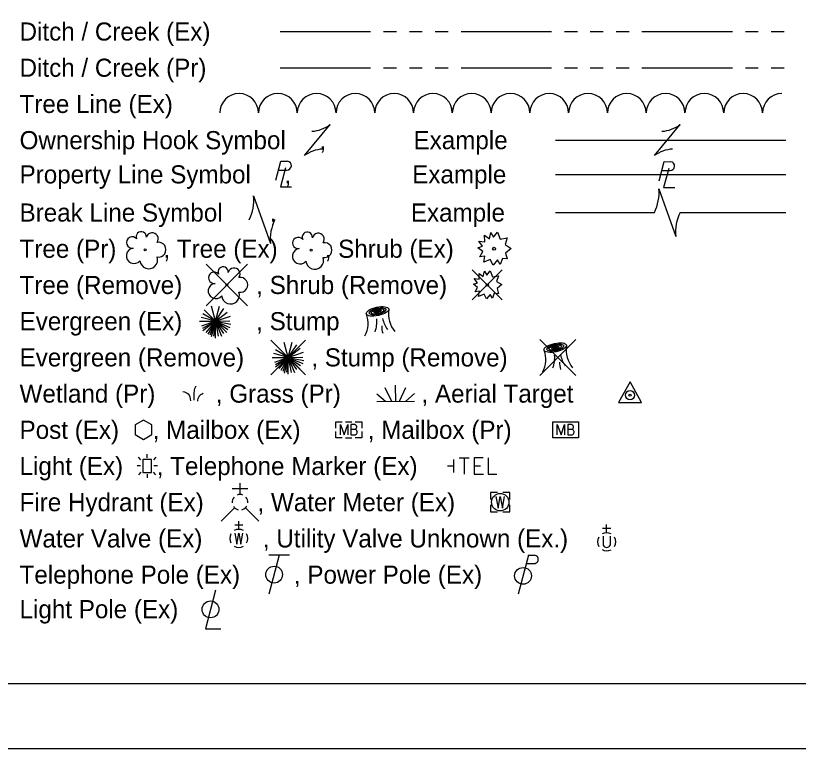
# Model space of a CAD drawing. Extents: x 0 to 34, y 0 to 22.
# Drawn here: x 8.23 to 14.29, y 0 to 5.67 of the extents above; entities that cross this region are included whole.
import ezdxf

# ---------------------------------------------------------------- set-up
doc = ezdxf.new("R2010")
doc.units = 0
for name, color, linetype in [('SH_Border', 7, 'Continuous'), ('SH_Cut_Line', 7, 'Continuous'), ('SH_Text', 7, 'Continuous')]:
    doc.layers.add(name, color=color, linetype=linetype)

msp = doc.modelspace()

# ---------------------------------------------------------------- linework, layer by layer
at = {"layer": 'SH_Border'}
msp.add_lwpolyline([(1.5, 21.5), (33.5, 21.5), (33.5, 0.5), (1.5, 0.5)], close=True, dxfattribs=at)
at = {"layer": 'SH_Cut_Line'}
msp.add_lwpolyline([(0, 0), (34, 0), (34, 22), (0, 22)], close=True, dxfattribs=at)
at = {"layer": 'SH_Text'}
for p, q in [((10.28, 5.5434), (10.98, 5.5434)), ((11.08, 5.5434), (11.18, 5.5434)), ((11.28, 5.5434), (11.38, 5.5434)), ((11.48, 5.5434), (11.58, 5.5434)), ((11.68, 5.5434), (12.38, 5.5434)), ((12.48, 5.5434), (12.58, 5.5434)), ((12.68, 5.5434), (12.78, 5.5434)), ((12.88, 5.5434), (12.98, 5.5434)), ((13.08, 5.5434), (13.78, 5.5434)), ((13.88, 5.5434), (13.98, 5.5434)), ((14.08, 5.5434), (14.18, 5.5434)), ((10.28, 5.2634), (10.98, 5.2634)), ((11.08, 5.2634), (11.18, 5.2634)), ((11.28, 5.2634), (11.38, 5.2634)), ((11.48, 5.2634), (11.58, 5.2634)), ((11.68, 5.2634), (12.38, 5.2634)), ((12.48, 5.2634), (12.58, 5.2634)), ((12.68, 5.2634), (12.78, 5.2634)), ((12.88, 5.2634), (12.98, 5.2634)), ((13.08, 5.2634), (13.78, 5.2634)), ((13.88, 5.2634), (13.98, 5.2634)), ((14.08, 5.2634), (14.18, 5.2634)), ((10.4674, 4.5834), (10.6674, 4.8234)), ((13.1756, 4.5834), (13.3756, 4.8234)), ((10.5674, 4.7034), (10.5674, 4.7034)), ((12.4101, 4.7034), (14.1924, 4.7034)), ((13.2756, 4.7034), (13.2756, 4.7034)), ((10.2676, 4.4724), (10.3325, 4.4724)), ((10.3077, 4.4412), (10.3077, 4.4412)), ((12.4101, 4.4388), (14.1924, 4.4388)), ((13.2333, 4.4683), (13.2981, 4.4683)), ((13.2734, 4.4371), (13.2734, 4.4371)), ((13.2106, 4.3276), (13.3406, 3.9593)), ((10.0749, 4.2719), (10.2049, 3.9037)), ((12.4101, 4.1434), (13.1757, 4.1434)), ((13.2756, 4.1435), (13.2756, 4.1435)), ((13.3755, 4.1434), (14.1924, 4.1434)), ((10.1399, 4.0878), (10.1399, 4.0878)), ((9.7078, 3.7437), (10.0285, 3.423)), ((10.0285, 3.7437), (9.7078, 3.423)), ((11.7669, 3.6993), (11.9986, 3.4675)), ((11.9986, 3.6993), (11.7669, 3.4675)), ((9.8681, 3.5834), (9.8681, 3.5834)), ((11.8827, 3.5834), (11.8827, 3.5834)), ((9.7786, 3.3032), (9.7477, 3.4185)), ((9.7786, 3.3032), (9.81, 3.4206)), ((9.7786, 3.3032), (9.845, 3.4003)), ((9.7786, 3.3032), (9.6683, 3.3327)), ((9.7786, 3.3032), (9.681, 3.3606)), ((9.7786, 3.3032), (9.6914, 3.3903)), ((9.7786, 3.3032), (9.87, 3.3733)), ((9.7786, 3.3032), (9.897, 3.3433)), ((9.6552, 3.3032), (9.7786, 3.3032)), ((9.7786, 3.3032), (9.6714, 3.2641)), ((9.7786, 3.3032), (9.679, 3.2461)), ((9.7786, 3.3032), (9.681, 3.2283)), ((9.7786, 3.3032), (9.705, 3.2165)), ((9.7786, 3.3032), (9.7207, 3.2028)), ((9.7786, 3.3032), (9.737, 3.1947)), ((9.7786, 3.3032), (9.747, 3.1817)), ((9.7786, 3.3032), (9.7651, 3.1884)), ((9.7786, 3.3032), (9.8914, 3.3055)), ((9.7786, 3.1722), (9.7786, 3.3032)), ((9.7786, 3.3032), (9.8017, 3.1872)), ((9.7786, 3.3032), (9.827, 3.1865)), ((9.7786, 3.3032), (9.842, 3.2083)), ((9.7786, 3.3032), (9.8683, 3.2151)), ((9.7786, 3.3032), (9.8742, 3.2393)), ((9.7786, 3.3032), (9.8902, 3.2546)), ((9.7786, 3.3032), (9.8993, 3.2792)), ((11.0523, 3.3034), (11.0523, 3.3034)), ((10.209, 3.157), (10.4763, 2.8897)), ((10.4763, 3.157), (10.209, 2.8897)), ((12.2888, 3.1624), (12.5669, 2.8843)), ((12.5669, 3.1624), (12.2888, 2.8843)), ((10.3426, 3.0234), (10.2554, 3.1106)), ((10.3426, 3.0234), (10.3118, 3.1387)), ((10.3426, 3.0234), (10.3741, 3.1408)), ((10.3426, 3.0234), (10.409, 3.1205)), ((10.3426, 3.0234), (10.4341, 3.0935)), ((10.3426, 3.0234), (10.2323, 3.053)), ((10.3426, 3.0234), (10.245, 3.0808)), ((10.3426, 3.0234), (10.4611, 3.0636)), ((10.2193, 3.0234), (10.3426, 3.0234)), ((10.3426, 3.0234), (10.2354, 2.9843)), ((10.3426, 3.0234), (10.2431, 2.9663)), ((10.3426, 3.0234), (10.245, 2.9485)), ((10.3426, 3.0234), (10.269, 2.9367)), ((10.3426, 3.0234), (10.2847, 2.923)), ((10.3426, 3.0234), (10.301, 2.9149)), ((10.3426, 3.0234), (10.3111, 2.902)), ((10.3426, 3.0234), (10.3291, 2.9086)), ((10.3426, 3.0234), (10.4554, 3.0257)), ((10.3426, 2.8924), (10.3426, 3.0234)), ((10.3426, 3.0234), (10.3657, 2.9075)), ((10.3426, 3.0234), (10.391, 2.9067)), ((10.3426, 3.0234), (10.4061, 2.9286)), ((10.3426, 3.0234), (10.4323, 2.9353)), ((10.3426, 3.0234), (10.4382, 2.9595)), ((10.3426, 3.0234), (10.4543, 2.9748)), ((10.3426, 3.0234), (10.4633, 2.9994)), ((10.3426, 3.0234), (10.3426, 3.0234)), ((12.4278, 3.0234), (12.4278, 3.0234)), ((12.4279, 3.0234), (12.4279, 3.0234)), ((11.1443, 2.683), (11.0921, 2.789)), ((11.1742, 2.6834), (11.1724, 2.8089)), ((11.2042, 2.6838), (11.2532, 2.7914)), ((11.0956, 2.6822), (11.0273, 2.7393)), ((11.253, 2.6846), (11.3195, 2.7437)), ((11.0281, 2.6812), (11.3203, 2.6856)), ((10.7854, 2.5245), (10.8355, 2.5245)), ((10.811, 2.4634), (10.811, 2.4634)), ((12.4891, 2.4634), (12.4891, 2.4634)), ((10.7854, 2.4023), (10.8355, 2.4023)), ((9.2031, 2.2318), (9.1846, 2.2506)), ((9.2513, 2.2474), (9.2513, 2.274)), ((9.318, 2.2506), (9.2994, 2.2318)), ((9.1992, 2.1837), (9.1726, 2.1837)), ((9.2513, 2.1834), (9.2513, 2.1834)), ((9.3301, 2.1837), (9.3034, 2.1837)), ((11.624, 2.1834), (11.5742, 2.1834)), ((11.624, 2.1334), (11.624, 2.2334)), ((9.2031, 2.135), (9.1846, 2.1162)), ((9.318, 2.1162), (9.2994, 2.135)), ((9.2513, 2.1194), (9.2513, 2.0928)), ((10.0294, 2.0066), (9.9094, 2.0066)), ((9.9694, 1.9636), (9.9694, 2.0496)), ((9.9694, 1.9034), (9.9694, 1.9034)), ((9.9694, 1.9034), (9.9694, 1.9034)), ((11.983, 1.9034), (11.983, 1.9034)), ((9.9271, 1.861), (9.8231, 1.7571)), ((10.0117, 1.861), (10.1157, 1.7571)), ((9.9603, 1.6934), (9.9603, 1.757)), ((9.992, 1.7252), (9.9285, 1.7252)), ((12.8382, 1.6988), (12.7746, 1.6988)), ((12.8065, 1.667), (12.8065, 1.7305)), ((12.7793, 1.6401), (12.7793, 1.5712)), ((12.8335, 1.6401), (12.8335, 1.5712)), ((9.9603, 1.6234), (9.9603, 1.6234)), ((12.8065, 1.597), (12.8065, 1.597)), ((10.2733, 1.4934), (10.193, 1.1934)), ((10.3533, 1.4934), (10.1933, 1.4934)), ((12.2023, 1.4934), (12.122, 1.1934)), ((12.2023, 1.4934), (12.2448, 1.4934)), ((12.1852, 1.4296), (12.2448, 1.4296))]:
    msp.add_line(p, q, dxfattribs=at)
for points in [[(10.2466, 4.3928), (10.2857, 4.5411), (10.3374, 4.541)], [(10.3211, 4.4892), (10.2815, 4.3414), (10.3688, 4.3414)], [(13.2123, 4.3887), (13.2514, 4.537), (13.303, 4.5369)], [(13.2867, 4.4851), (13.2471, 4.3373), (13.3344, 4.3373)], [(11.9315, 3.9539), (11.9617, 3.9906), (11.9825, 3.938), (12.0371, 3.947), (12.0201, 3.8964), (12.0674, 3.8666), (12.0246, 3.8299), (12.0371, 3.7842), (11.9994, 3.7876), (11.9831, 3.742), (11.9617, 3.7766), (11.9278, 3.7357), (11.9064, 3.7801), (11.8554, 3.7586), (11.865, 3.8056), (11.8244, 3.8015), (11.8481, 3.841), (11.8096, 3.8694), (11.8466, 3.8826), (11.8162, 3.9227), (11.8628, 3.9172), (11.8613, 3.9691), (11.899, 3.9407), (11.9093, 3.99), (11.9315, 3.9539)], [(11.8791, 3.6603), (11.9049, 3.6916), (11.9225, 3.6468), (11.9689, 3.6544), (11.9545, 3.6114), (11.9947, 3.5862), (11.9583, 3.5549), (11.9689, 3.5161), (11.9369, 3.519), (11.9231, 3.4802), (11.9049, 3.5096), (11.876, 3.4749), (11.8578, 3.5126), (11.8145, 3.4943), (11.8226, 3.5343), (11.7881, 3.5308), (11.8082, 3.5643), (11.7756, 3.5885), (11.807, 3.5997), (11.7812, 3.6338), (11.8208, 3.6291), (11.8195, 3.6733), (11.8515, 3.6491), (11.8603, 3.691), (11.8791, 3.6603)], [(9.1581, 2.4259), (9.223, 2.3884), (9.288, 2.4259), (9.288, 2.5009), (9.223, 2.5384), (9.1581, 2.5009), (9.1581, 2.4259)], [(10.711, 2.476), (10.711, 2.5245), (10.7595, 2.5245)], [(10.7462, 2.4234), (10.7462, 2.5034), (10.7751, 2.4234), (10.8029, 2.5034), (10.8029, 2.4234)], [(10.8621, 2.4669), (10.8652, 2.47), (10.8671, 2.4719), (10.8684, 2.4738), (10.869, 2.475), (10.8703, 2.4776), (10.8709, 2.4795), (10.8722, 2.4839), (10.8722, 2.4858), (10.8722, 2.4883), (10.8715, 2.4921), (10.8703, 2.4952), (10.8684, 2.4977), (10.8652, 2.5002), (10.8627, 2.5015), (10.8614, 2.5021), (10.8583, 2.5034), (10.8274, 2.5034), (10.8274, 2.4234), (10.8621, 2.4234), (10.8665, 2.4259), (10.8703, 2.4291), (10.8734, 2.4341), (10.8753, 2.4398), (10.8759, 2.4454), (10.8759, 2.4492), (10.8747, 2.453), (10.8722, 2.4587), (10.869, 2.4624), (10.8621, 2.4669), (10.8274, 2.4669)], [(10.8613, 2.5245), (10.911, 2.5245), (10.911, 2.476)], [(12.4243, 2.4234), (12.4243, 2.5034), (12.4533, 2.4234), (12.481, 2.5034), (12.481, 2.4234)], [(12.5402, 2.4669), (12.5433, 2.47), (12.5452, 2.4719), (12.5465, 2.4738), (12.5471, 2.475), (12.5484, 2.4776), (12.549, 2.4795), (12.5503, 2.4839), (12.5503, 2.4858), (12.5503, 2.4883), (12.5496, 2.4921), (12.5484, 2.4952), (12.5465, 2.4977), (12.5433, 2.5002), (12.5408, 2.5015), (12.5396, 2.5021), (12.5364, 2.5034), (12.5056, 2.5034), (12.5056, 2.4234), (12.5402, 2.4234), (12.5446, 2.4259), (12.5484, 2.4291), (12.5515, 2.4341), (12.5534, 2.4398), (12.5541, 2.4454), (12.5541, 2.4492), (12.5528, 2.453), (12.5503, 2.4587), (12.5471, 2.4624), (12.5402, 2.4669), (12.5056, 2.4669)], [(10.7595, 2.4023), (10.711, 2.4023), (10.711, 2.4508)], [(10.911, 2.4508), (10.911, 2.4023), (10.8613, 2.4023)], [(11.6648, 2.2455), (11.7426, 2.2455)], [(11.7042, 2.2455), (11.7042, 2.1205)], [(11.8498, 2.2455), (11.7819, 2.2455), (11.7819, 2.1205), (11.8547, 2.1205)], [(11.8892, 2.2455), (11.8892, 2.1205), (11.9571, 2.1205)], [(11.7819, 2.1835), (11.8301, 2.1835)], [(11.963, 1.9784), (11.908, 1.9784), (11.908, 1.9234)], [(11.9497, 1.9484), (11.9663, 1.8584), (11.983, 1.9484), (11.9997, 1.8584), (12.0163, 1.9484)], [(12.058, 1.9234), (12.058, 1.9784), (12.003, 1.9784)], [(11.908, 1.8834), (11.908, 1.8284), (11.963, 1.8284)], [(12.003, 1.8284), (12.058, 1.8284), (12.058, 1.8834)], [(9.9285, 1.6644), (9.9444, 1.5782), (9.9603, 1.6644), (9.9763, 1.5782), (9.9921, 1.6644)], [(9.7806, 1.2221), (9.7018, 0.9229), (9.82, 0.9229)]]:
    msp.add_lwpolyline(points, dxfattribs=at)
for points in [[(12.8973, 2.6734), (13.0773, 2.6734), (12.9873, 2.8344)], [(12.3891, 2.5245), (12.5891, 2.5245), (12.5891, 2.4023), (12.3891, 2.4023)], [(9.218, 2.1334), (9.2846, 2.1334), (9.2846, 2.2334), (9.218, 2.2334)]]:
    msp.add_lwpolyline(points, close=True, dxfattribs=at)
for centre, radius in [((9.2351, 3.8553), 0.0084), ((10.5197, 3.8518), 0.0072), ((11.9357, 3.8634), 0.0115), ((9.8681, 3.5834), 0.0072), ((11.8827, 3.5834), 0.00979), ((12.9873, 2.7312), 0.035), ((12.9873, 2.7312), 0.008), ((11.983, 1.9034), 0.0675), ((10.2332, 1.3434), 0.065), ((12.1595, 1.3334), 0.065), ((9.7412, 1.0745), 0.065)]:
    msp.add_circle(centre, radius, dxfattribs=at)
for centre, radius, start, end in [((9.9624, 4.9134), 0.15, 0.00982, 179.99264), ((10.2623, 4.9134), 0.15, 0.00982, 179.99264), ((10.5623, 4.9134), 0.15, 0.00982, 179.99264), ((10.8623, 4.9134), 0.15, 0.00982, 179.99264), ((11.1623, 4.9134), 0.15, 0.00982, 179.99264), ((11.4623, 4.9134), 0.15, 0.00982, 179.99264), ((11.7623, 4.9134), 0.15, 0.00982, 179.99264), ((12.0623, 4.9134), 0.15, 0.00982, 179.99264), ((12.3623, 4.9134), 0.15, 0.00982, 179.99264), ((12.6623, 4.9134), 0.15, 0.00982, 179.99264), ((12.9623, 4.9134), 0.15, 0.00982, 179.99264), ((13.2623, 4.9134), 0.15, 0.00982, 179.99264), ((13.5623, 4.9134), 0.15, 0.00982, 179.99264), ((13.8623, 4.9134), 0.15, 0.00982, 179.99264), ((14.1623, 4.9134), 0.15, 89.99552, 179.99264), ((10.5092, 5.0383), 0.2668, 273.69448, 306.33701), ((13.2175, 5.0383), 0.2668, 273.69448, 306.33701), ((10.6255, 4.3684), 0.2668, 93.69448, 126.33701), ((13.3337, 4.3684), 0.2668, 93.69448, 126.33701), ((10.3322, 4.5069), 0.0345, 270.47098, 81.3281), ((13.2978, 4.5028), 0.0345, 270.47098, 81.3281), ((12.8786, 4.2951), 0.3335, 332.94224, 5.58476), ((9.743, 4.2395), 0.3335, 332.94224, 5.58476), ((13.6725, 3.9918), 0.3335, 152.94224, 185.58476), ((10.5369, 3.9362), 0.3335, 152.94224, 185.58476), ((9.1358, 3.9112), 0.0441, 39.06254, 279.54124), ((9.2056, 3.9563), 0.0395, 354.0047, 205.97412), ((9.2899, 3.9402), 0.0466, 323.82996, 165.0376), ((10.4204, 3.9077), 0.0441, 39.06254, 279.54124), ((10.4902, 3.9529), 0.0395, 354.0047, 205.97412), ((10.5745, 3.9367), 0.0466, 323.82996, 165.0376), ((9.3389, 3.8564), 0.0574, 259.14531, 101.45961), ((10.6235, 3.8529), 0.0574, 259.14531, 101.45961), ((9.1495, 3.8088), 0.0592, 96.17219, 320.57371), ((10.4341, 3.8054), 0.0592, 96.17219, 320.57371), ((9.2635, 3.7771), 0.0685, 184.94757, 19.45715), ((10.5481, 3.7737), 0.0685, 184.94757, 19.45715), ((9.8386, 3.6844), 0.0395, 354.0047, 205.97412), ((9.9229, 3.6682), 0.0466, 323.82996, 165.0376), ((9.7688, 3.6393), 0.0441, 39.06254, 279.54124), ((9.9719, 3.5844), 0.0574, 259.14531, 101.45961), ((9.7825, 3.5369), 0.0592, 96.17219, 320.57371), ((9.8965, 3.5052), 0.0685, 184.94757, 19.45715), ((11.3325, 3.3604), 0.2146, 171.41061, 219.91939), ((10.7607, 3.2861), 0.2001, 331.53375, 20.92689), ((10.7764, 3.3047), 0.2527, 340.79377, 3.54808), ((11.3777, 3.4062), 0.316, 194.9653, 212.12159), ((11.2475, 3.2634), 0.1819, 178.79264, 197.12241), ((12.7081, 3.0804), 0.2146, 171.41061, 219.91939), ((12.1363, 3.0061), 0.2001, 331.53375, 20.92689), ((12.152, 3.0247), 0.2527, 340.79377, 3.54808), ((12.7532, 3.1262), 0.316, 194.9653, 212.12159), ((12.6231, 2.9834), 0.1819, 178.79264, 197.12241), ((9.9694, 1.9034), 0.06, 140.02099, 184.06293), ((9.9694, 1.9034), 0.06, 68.13946, 112.03798), ((9.9694, 1.9034), 0.06, 356.01648, 39.98885), ((9.9694, 1.9034), 0.06, 211.87877, 255.84793), ((9.9694, 1.9034), 0.06, 283.82389, 329.90967), ((9.9603, 1.6235), 0.07, 150.01836, 209.98164), ((9.9603, 1.6235), 0.07, 60.01836, 120.01574), ((9.9603, 1.6235), 0.07, 330.01836, 29.98164), ((12.8064, 1.597), 0.07, 60.01836, 120.01574), ((12.8064, 1.597), 0.07, 150.01836, 209.98164), ((12.8064, 1.597), 0.07, 330.01836, 29.98164), ((9.9603, 1.6235), 0.07, 239.98426, 299.98164), ((12.8064, 1.597), 0.07, 239.98426, 299.98164), ((12.8064, 1.5839), 0.03, 205.19243, 334.80757), ((12.2454, 1.4615), 0.0319, 268.8767, 91.1233)]:
    msp.add_arc(centre, radius, start, end, dxfattribs=at)
for centre, major_axis in [((11.0335, 3.3789), (0.0868, 0.0187)), ((11.0335, 3.3789), (0.0651, 0.0141)), ((11.0335, 3.3789), (0.0488, 0.0105)), ((11.0335, 3.3789), (0.0275, 0.0059)), ((11.0335, 3.3789), (0.0154, 0.0033)), ((12.4091, 3.0989), (0.0868, 0.0187)), ((12.4091, 3.0989), (0.0651, 0.0141)), ((12.4091, 3.0989), (0.0488, 0.0105)), ((12.4091, 3.0989), (0.0275, 0.0059)), ((12.4091, 3.0989), (0.0154, 0.0033))]:
    msp.add_ellipse(centre, major_axis=major_axis, ratio=0.36865, dxfattribs=at)
for points in [[(9.6147, 2.692), (9.6147, 2.7393), (9.6206, 2.7837), (9.6294, 2.8045)], [(9.5274, 2.759), (9.5688, 2.7413), (9.5865, 2.688)], [(9.6424, 2.6848), (9.6543, 2.7232), (9.6838, 2.747)]]:
    msp.add_spline(points, degree=3, dxfattribs=at)

# ---------------------------------------------------------------- texts
for s, p in [('Ditch / Creek (Ex)', (8.2638, 5.4734)), ('Ditch / Creek (Pr)', (8.2638, 5.1934)), ('Tree Line (Ex)', (8.2638, 4.9134)), ('Ownership Hook Symbol     ,             Example', (8.2638, 4.6334)), ('Property Line Symbol     ,                  Example', (8.2638, 4.3688)), ('Break Line Symbol       ,                    Example', (8.2638, 4.0734)), ('Tree (Pr)       , Tree (Ex)       , Shrub (Ex)', (8.2638, 3.7934)), ('Tree (Remove)           , Shrub (Remove)', (8.2638, 3.5134)), ('Evergreen (Ex)           , Stump ', (8.2638, 3.2334)), ('Evergreen (Remove)          , Stump (Remove)', (8.2638, 2.9534)), ('Wetland (Pr)         , Grass (Pr)            , Aerial Target    ', (8.2638, 2.6734)), ('Post (Ex)     , Mailbox (Ex)          , Mailbox (Pr)', (8.2638, 2.3934)), ('Light (Ex)     , Telephone Marker (Ex)     ', (8.2638, 2.1134)), ('Fire Hydrant (Ex)        , Water Meter (Ex)', (8.2638, 1.8334)), ('Water Valve (Ex)         , Utility Valve Unknown (Ex.)', (8.2638, 1.5534)), ('Telephone Pole (Ex)        , Power Pole (Ex)', (8.2638, 1.2734)), ('Light Pole (Ex)     ', (8.2638, 1.0063))]:
    msp.add_text(s, height=0.14, dxfattribs=at).set_placement(p)

doc.saveas('drawing.dxf')
